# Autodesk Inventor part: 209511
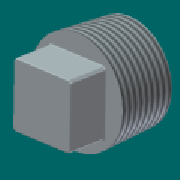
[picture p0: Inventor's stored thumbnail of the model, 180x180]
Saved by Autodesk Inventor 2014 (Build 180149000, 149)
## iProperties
Shininess: 64.0
Length Units: 11272
Angle Units: 11279
Time Units: 11290
Mass Units: 11286
Length Display Precision: 3
Angle Display Precision: 2
Company: Autodesk, Inc.
Created: 2002-05
Part Number: 209511
Material: Steel, Mild
Description: Fitting; MC-B2-S
Document SubType Name: Modeling
Designer: Autodesk, Inc.
Density: 1 g/cm^3
Appearance: Yellow Zinc
Density: 0.0
Volumn: 0.0
Area: 0.0
PropertySet Name: Model Information
Control State: 0
Master: False
Checked Out: False
Last Check In By: JT
Last Check In Date: 2003-06-20
Title: Fitting; MC-B2-S
Author: Autodesk, Inc.
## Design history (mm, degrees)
sketch "Sketch1"
  geometry: C1 r 5.144 at (0, 0)
  constraints: 1 centre point, 1 other
  dimensions: "d6" = 10.287 diameter of C1 (= Dia)
extrude "Threaded" new body sketch "Sketch1" distance "d7" = 9.525 (= Thd_Len); taper "d8" = -3.5 deg
thread "Thread1" dims "d9" = 25.4, "d10" = 0
sketch "Sketch5"
  geometry: L1 (-5.563, 5.563)-(5.563, 5.563); L2 (5.563, 5.563)-(5.563, -5.563); L3 (5.563, -5.563)-(-5.563, -5.563); L4 (-5.563, -5.563)-(-5.563, 5.563); L5 (-5.563, -5.563)-(5.563, 5.563); C1 r 5.144 at (0, 0) reference; 1 further point
  constraints: 10 end point, 2 parallel, 2 perpendicular, 1 coincident, 1 horizontal, 1 midpoint
  dimensions: "d11" = 11.1252 distance of L1.end L2.end (= Head_Wd)
extrude "Square Ext" join sketch "Sketch5" distance "d12" = 6.35 (= Head_Ht); taper "d13" = 0 deg
chamfer "Square Chamf" distance "d14" = 0.762; stored, may be unused: second distance "d15" = 0.762, angle "d30" = 45 deg
fillet "Fillet1" dims "d16" = 0.381, "d17" = 0.381
sketch "Sketch6"
  geometry: L1 (3.212, 5.563)-(6.423, 0); L2 (6.423, 0)-(3.212, -5.563); L3 (3.212, -5.563)-(-3.212, -5.563); L4 (-3.212, -5.563)-(-6.423, 0); L5 (-6.423, 0)-(-3.212, 5.563); L6 (-3.212, 5.563)-(3.212, 5.563); C1 r 5.144 at (0, 0) reference; 2 further points
  constraints: 12 end point, 1 coincident, 1 midpoint, 1 vertical alignment, 11 other
  dimensions: "d18" = 11.1252 distance between parallel lines of L3 L6 (= Head_Wd)
extrude "Hex Ext" join sketch "Sketch6" distance "d19" = 6.35 (= Head_Ht); taper "d20" = 0 deg
sketch "Sketch8"
  geometry: L1 (-6.423, 6.35)-(-3.212, 6.35) reference; L2 (-6.423, 0)-(-3.212, 0) reference; L3 (-5.563, 6.35)-(-15.088, 3.798); L4 (-5.563, 0)-(-15.088, 2.552); L5 (0, 0)-(0, 11.515); L6 (-15.088, 3.798)-(-15.088, 6.35); L7 (-15.088, 6.35)-(-6.423, 6.35); L8 (-15.088, 2.552)-(-15.088, 0); L9 (-15.088, 0)-(-6.423, 0)
  constraints: 14 end point, 4 perpendicular, 2 point on line, 1 collinear, 1 parallel, 1 vertical alignment
  dimensions: "d25" = 11.1252 diameter of L3.start L5 (= Head_Wd); "d26" = 9.525 distance from line of L6 L3.start; "d28" = 15 deg angle of L3 L1; "d29" = 15 deg angle of L9 L4
revolve "Revolution3" sketch "Sketch8" stored, may be unused: angle "d27" = 90 deg
body "Solid1"
other parameters: "Thd_Len" = 9.525 [user parameter; used in 1 equation term], "Head_Ht" = 6.35 [user parameter; used in 2 equation terms], "Head_Wd" = 11.1252 [user parameter; used in 3 equation terms], "Dia" = 10.287 [user parameter; used in 1 equation term]
